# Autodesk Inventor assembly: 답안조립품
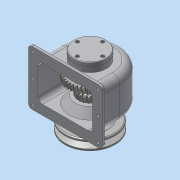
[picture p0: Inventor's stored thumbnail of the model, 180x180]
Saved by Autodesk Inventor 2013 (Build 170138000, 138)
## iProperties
Created: 2015-09
Part Number: 답안조립품
Document SubType Name: Assembly
Designer: ST4
Author: ST4
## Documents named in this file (14)
- C:\Users\ST4\Desktop\450907V1018\답안조립품.iam
- C:\Users\ST4\Desktop\450907V1018\1-본체.ipt
- C:\Users\ST4\Desktop\450907V1018\축.ipt
- C:\Users\ST4\Desktop\450907V1018\베어링 6203.ipt
- C:\Users\ST4\Desktop\450907V1018\키 - 6 x 6 x 22.ipt
- C:\Users\ST4\Desktop\450907V1018\스퍼기어.ipt
- C:\Users\ST4\Desktop\450907V1018\뒤커버.ipt
- C:\Users\ST4\Desktop\450907V1018\앞커버.ipt
- C:\Users\ST4\Desktop\450907V1018\오일 실 17 32 8.ipt
- C:\Users\ST4\Desktop\450907V1018\키 - 5 x 5 x 18.ipt
- C:\Users\ST4\Desktop\450907V1018\멈춤나사 - M4x10.ipt
- C:\Users\ST4\Desktop\450907V1018\V-벨트풀리.ipt
- C:\Users\ST4\Desktop\450907V1018\볼트 M3 x 10.ipt
- C:\Users\ST4\Desktop\450907V1018\볼트 M3 x 8.ipt
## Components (10 placed, 4 different names)
1. 1-본체:1
2. V-벨트풀리:1 — 각도:4, 플러쉬:1
3. ISO 4762 M3 x 10:1
4. ISO 4762 M3 x 10:2
5. ISO 4762 M3 x 10:3
6. ISO 4762 M3 x 10:4
7. ISO 4762 M3 x 8:1
8. ISO 4762 M3 x 8:2
9. ISO 4762 M3 x 8:3
10. ISO 4762 M3 x 8:4
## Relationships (2: Angle 1, Flush 1)
- 각도:4 [Angle]: V-벨트풀리:1
- 플러쉬:1 [Flush]: V-벨트풀리:1
